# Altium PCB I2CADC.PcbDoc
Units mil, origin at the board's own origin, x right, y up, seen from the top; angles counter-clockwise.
Board outline 1475 x 800 mil, 2 copper layers (Top Layer, Bottom Layer), stack 61.855 mil thick; 14 components, 9 nets, 44 pads, 7 vias.
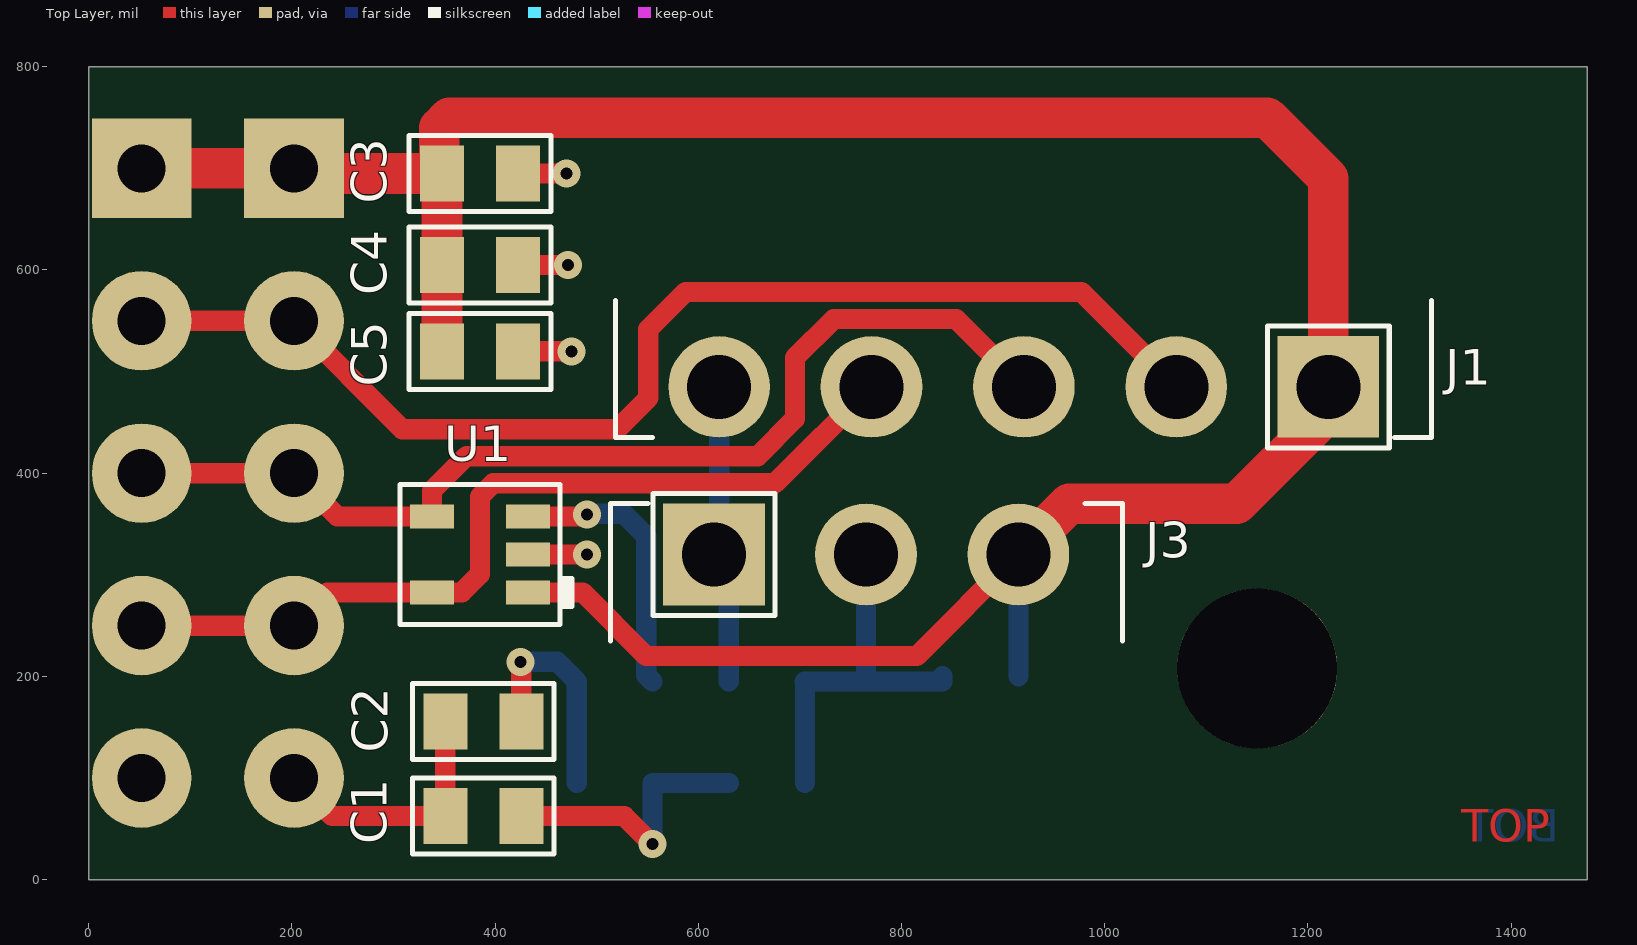
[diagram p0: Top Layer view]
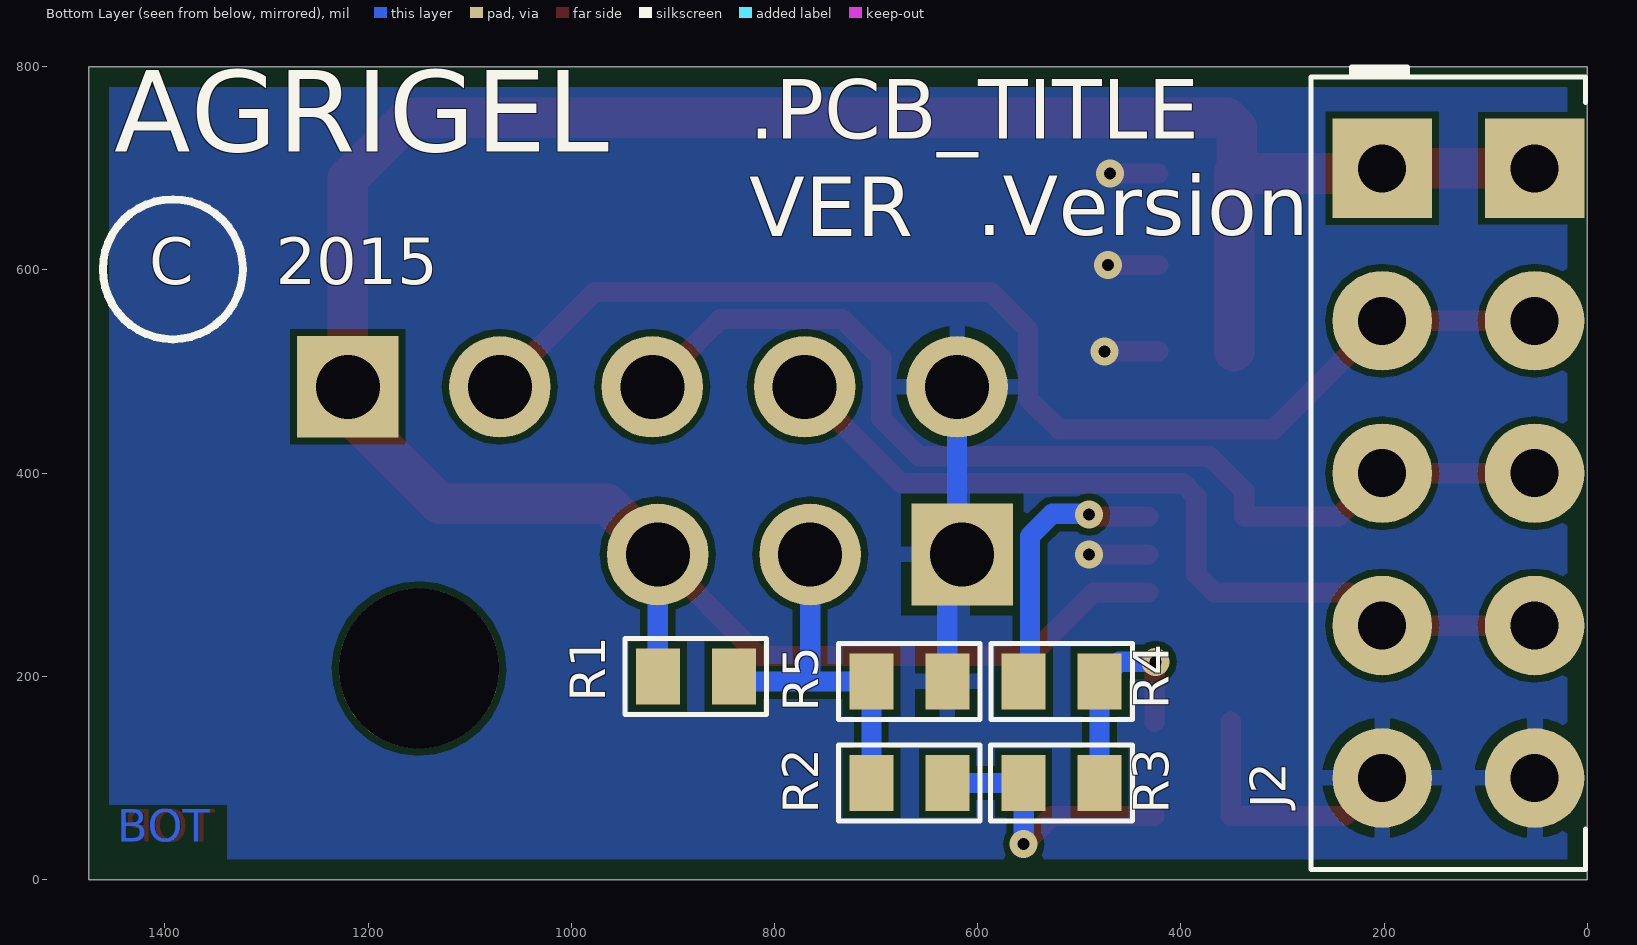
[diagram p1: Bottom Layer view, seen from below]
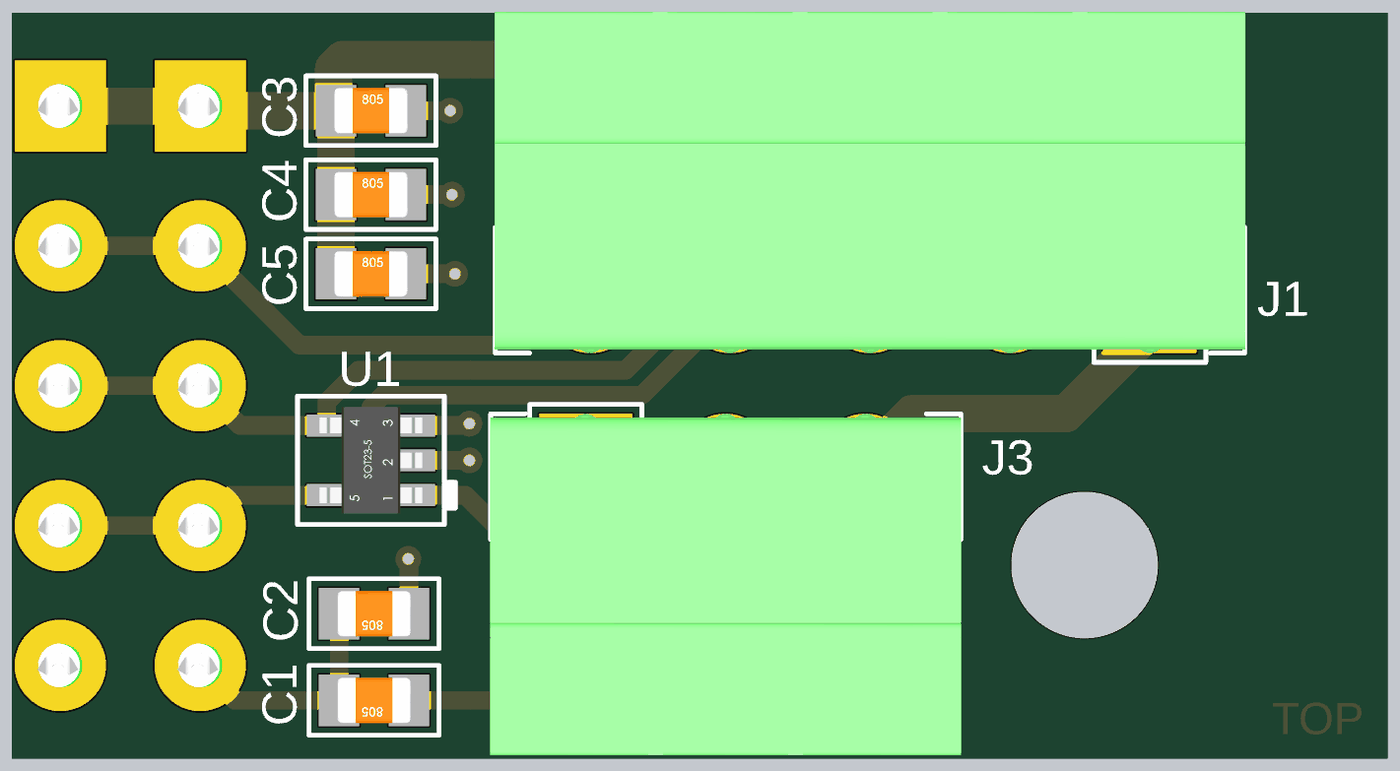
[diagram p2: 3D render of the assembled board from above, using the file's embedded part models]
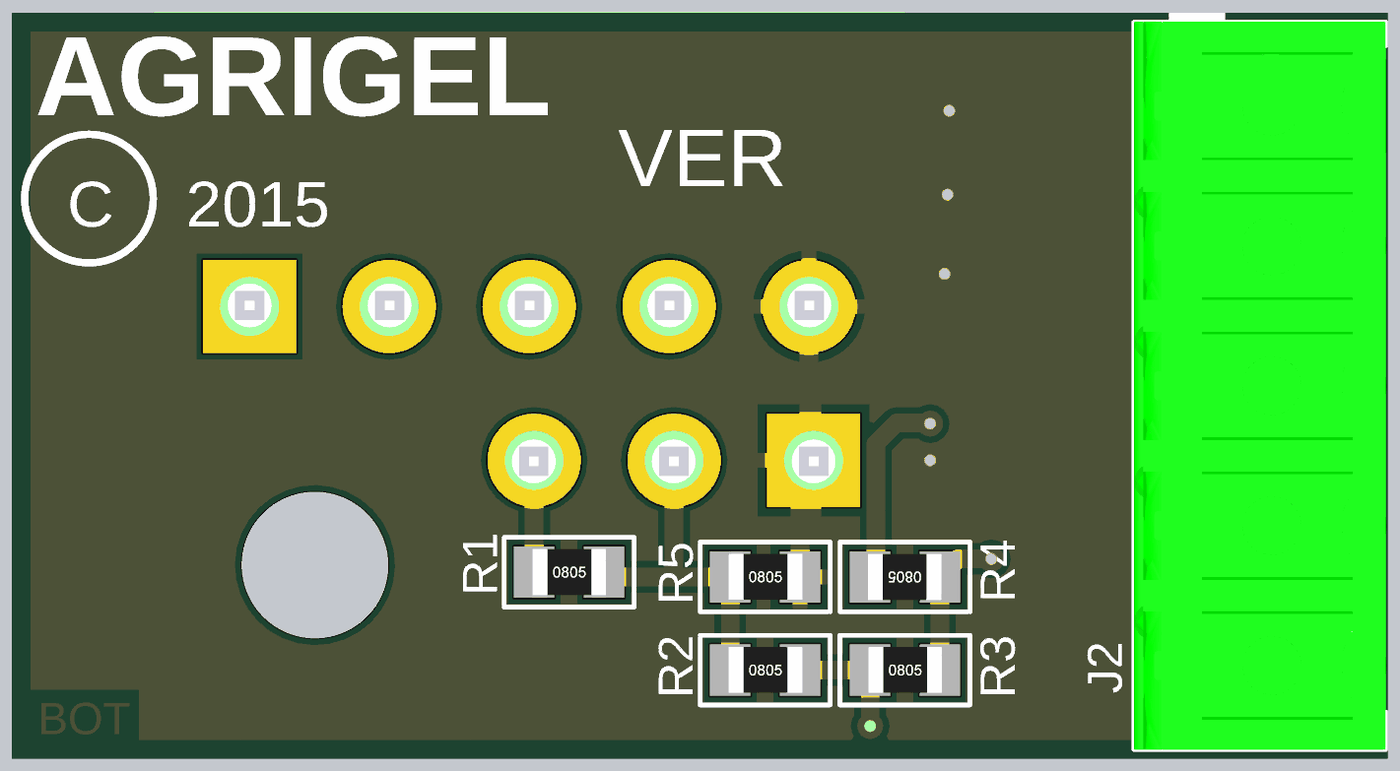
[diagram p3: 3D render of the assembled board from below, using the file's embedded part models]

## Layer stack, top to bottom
Top Layer: signal copper 1.4
Dielectric: prepreg 59.0551, FR-4, Dk 4.2
Bottom Layer: signal copper 1.4

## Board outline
0,0 0,800 1475,800 1475,0

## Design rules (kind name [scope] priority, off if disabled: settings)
Clearance [All] p1: gap=6.69
FabricationTestPointUsage TestPointUsage [All] p1: valid=0 allowmultiple=FALSE
FabricationTestpoint Testpoint [All] p1: side=3 testpointundercomponent=TRUE minsize=40 maxsize=100 preferedsize=60 minholesize=0 maxholesize=40 preferedholesize=32 testpointgrid=1 allowsidetop=TRUE allowsidebottom=TRUE usegrid=TRUE gridtolerance=0.01
HoleSize [All] p1: absolutevalues=TRUE maxlimit=196.85 minlimit=9.84 maxpercent=80.000 minpercent=20.000
PlaneClearance [All] p1: clearance=19.68
PolygonConnect PolygonConnectVia [All vs isvia] p1: connectstyle=Direct reliefconductorwidth=9.84 reliefentries=4 polygonreliefangle="90 Angle" airgapwidth=10
PolygonConnect [All] p2: connectstyle=Relief reliefconductorwidth=15.75 reliefentries=4 polygonreliefangle="90 Angle" airgapwidth=10
RoutingCorners [All] p1: cornerstyle=45-Degree minsetback=98.43 maxsetback=98.43
RoutingVias [All] p1: holewidth=11.81 width=27.56 viastyle="Through Hole" minholewidth=11.81 minwidth=27.56 maxholewidth=11.81 maxwidth=27.56
SilkToSolderMaskClearance SilkscreenOverComponentPads [IsPad] p1: minsilkscreentomaskgap=10 clearancetoexposedcopper=TRUE
SolderMaskExpansion [All] p1: expansion=1.97
Width "Width_High Power" [InNetClass('High Power')] p1: maxlimit=59.06 minlimit=19.68 preferedwidth=39.37
Width Width_Power [InNetClass('Power')] p2: maxlimit=39.37 minlimit=11.81 preferedwidth=19.68
Width [All] p3: maxlimit=78.74 minlimit=7.87 preferedwidth=7.87
22 further rules are at their usual default settings.

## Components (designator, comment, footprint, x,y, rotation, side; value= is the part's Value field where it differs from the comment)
C1 "100nF_C0805_50V_10%_X7R" CAPC0805X110N 388.33,62.55 r180 top
C2 "100nF_C0805_50V_10%_X7R" CAPC0805X110N 388.33,155.5 r180 top
C3 "100nF_C0805_50V_10%_X7R" CAPC0805X110N 385,695 r0 top
C4 "10nF_C0805_50V_10%_X7R" CAPC0805X110N 385,605 r0 top
C5 "1uF_C0805_50V_10%_X7R-DNF" CAPC0805X110N 385,520 r0 top
J1 "ECH381R-05P" ECH381R-05P 920,620 r0 top
J2 "IMCV 1,5/ 5-G-3,81" "IMCV 1,5/ 5-G-3,81" 127,400 r270 bottom
J3 "ECH381R-03P" ECH381R-03P 765.39,185 r180 top
R1 "10K_R0805_1%-DNF" RESC0805X65N 877.6,200 r180 bottom
R2 "1K_R0805_1%" RESC0805X65N 667.4,95 r180 bottom
R3 "1K_R0805_1%" RESC0805X65N 517.6,95 r180 bottom
R4 "1K_R0805_1%" RESC0805X65N 517.4,195 r0 bottom
R5 "10K_R0805_1%" RESC0805X65N 667.4,195 r180 bottom
U1 "MCP3021A0T-E/OT" SOT23-5 385,320 r180 top

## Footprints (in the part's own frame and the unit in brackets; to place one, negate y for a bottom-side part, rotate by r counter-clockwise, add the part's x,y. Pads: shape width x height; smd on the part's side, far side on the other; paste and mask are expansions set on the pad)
CAPC0805X110N [mm] "Chip Capacitor, 0805, 2-Leads, Body 2.0x1.3mm, IPC Medium Density"
  rect 1.1x1.4 smd paste+0 mask+0.05: 1(-0.95,0) 2(0.95,0)
  silkscreen extent -1.77,-0.95 1.77,0.95, body extent -1,-0.62 1,0.63, height 1.11
ECH381R-03P [mm] "ECH381R 12.22x9.2mm"
  rect 2.54x2.54 hole 1.6: 1(3.81,-3.429)
  round 2.54 hole 1.6: 2(0.01,-3.429) 3(-3.8,-3.429)
  silkscreen extent -6.4,-4.95 6.4,-1.27, body extent -6.41,-4.7 6.41,4.6, height 7.25
ECH381R-05P [mm] "ECH381R 19.84x9.2mm"
  rect 2.54x2.54 hole 1.6: 1(7.62,-3.429)
  round 2.54 hole 1.6: 2(3.82,-3.429) 3(0.01,-3.429) 4(-3.8,-3.429) 5(-7.61,-3.429)
  silkscreen extent -10.2,-4.95 10.2,-1.27, body extent -10.22,-4.7 10.22,4.6, height 7.25
"IMCV 1,5/ 5-G-3,81" [mil] "IMCV 1,5/ 5-G-3,81"
  rect 98x98 hole 47.24: 1(-300,-75) 1(-300,75)
  round 98 hole 47.24: 2(-150,-75) 2(-150,75) 3(0,-75) 3(0,75) 4(150,-75) 4(150,75) 5(300,-75) 5(300,75)
  silkscreen extent -400,-145 390,125, body extent -391,-145 391,125, height 571
RESC0805X65N [mm] "Chip Resistor, 0805, 2-Leads, Body 2.0x1.3mm, IPC Medium Density"
  rect 1.1x1.4 smd paste+0 mask+0.05: 1(-0.95,0) 2(0.95,0)
  silkscreen extent -1.77,-0.95 1.77,0.95, body extent -0.99,-0.62 1.01,0.63, height 0.6
SOT23-5 [mm] "SOT23, 5-Leads, Body 3.0x3.0mm (max), Pitch 0.95mm, IPC Medium Density"
  rect 1.1x0.6 smd paste+0 mask+0.05: 1(-1.2,0.95) 2(-1.2,0) 3(-1.2,-0.95) 4(1.2,-0.95) 5(1.2,0.95)
  silkscreen extent -2.3,-1.75 2,1.75, body extent -1.4,-1.45 1.4,1.45, height 1.14

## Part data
C1 C2 C3: library part 100nF_0805N_50V_10%_X7R_V, "Cap Ceramic X7R"
C4: library part 10nF_0805N_50V_10%_X7R_V, "Cap Ceramic X7R"
C5: library part 1uF_0805N_50V_10%_X7R_V-DNF, "Cap Ceramic X7R - Do not Fit"
J1 J3: "Header Pluggable 3.81mm Rt Angle"
J2: "Header Pluggable 3.81mm Vertical Female"
R1: library part 10K_0805_v-DNF, "Resistor Chip SMD - Do not Fit"
R2 R3 R4: library part 1K_0805_H, "Resistor Chip SMD"
R5: library part 10K_0805_V, "Resistor Chip SMD"
U1: library part MCP3021A0T-E/OT_SOT23, "IC 10-Bit A/D Converter with I2C"

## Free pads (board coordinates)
  round 157.48 hole 157.48 unplated mask+1: 0(1150,207.68)

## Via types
v1: diameter 27.56, hole 11.81, Top Layer to Bottom Layer, tented both sides, 7 vias

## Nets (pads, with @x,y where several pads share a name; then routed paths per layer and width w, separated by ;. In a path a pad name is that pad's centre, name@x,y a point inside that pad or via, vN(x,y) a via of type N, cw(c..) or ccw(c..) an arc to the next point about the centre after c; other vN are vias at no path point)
GND: C1.2 C2.2 C3.2 C4.2 C5.2 J1.5 J2.5 J3.1 R5.2 U1.2 | length 772.1
  Top Layer w20: J2.5@202,100 239.45,62.55 C1.2 C2.2 ; C5.2 v1(475.08,520) ; C4.2 v1(471.87,605) ; C3.2 v1(470,695) ; U1.2 v1(490.52,320)
  Bottom Layer w20: J1.5 620.39,325 J3.1 630,320 R5.2
NetC1_1: C1.1 R2.2 R3.1 | length 275.6
  Top Layer w20: C1.1 527.26,62.55 v1(554.8,35)
  Bottom Layer w19.68: R3.1 R2.2
  Bottom Layer w20: v1(554.8,35) 554.8,94.8 R3.1
NetC2_1: C2.1 R3.2 R4.1 | length 222.2
  Top Layer w20: v1(425,214.27) 425.73,213.54 C2.1
  Bottom Layer w20: v1(425,214.27) 460.93,214.27 480.2,195 R3.2
NetJ1_2: J1.2 J2.2 | length 1196.7
  Top Layer w20: J2.2@52,550 202,550 308.61,443.39 520,443.39 550.62,474.01 550.62,541.54 587.47,578.39 977.01,578.39 J1.2
NetJ1_3: J1.3 J2.3 U1.4 | length 1044.3
  Top Layer w20: J2.3@52,400 202,400 244.6,357.4 U1.4 337.76,382.76 371.69,416.69 658.33,416.69 695,453.36 695,513.62 733.07,551.69 853.7,551.69 J1.3
NetJ1_4: J1.4 J2.4 U1.5 | length 860.6
  Top Layer w20: J2.4@52,250 202,250 234.6,282.6 U1.5 367.28,282.6 385,300.31 385,376.99 398.01,390 675.39,390 J1.4
NetJ3_2: J3.2 R1.2 R2.1 R5.1 | length 365.4
  Bottom Layer w19.68: R2.1 R5.1
  Bottom Layer w20: R5.1 765,195 ; J3.2 765,195 ; R1.2 840.2,195 765,195
NetR4_2: R4.2 U1.3 | length 272.1
  Top Layer w20: U1.3 488.55,357.4 v1(490.52,359.37)
  Bottom Layer w20: v1(490.52,359.37) 491.15,360 526.61,360 548.7,337.91 548.7,201.1 R4.2
VCC: C3.1 C4.1 C5.1 J1.1 J2.1 J3.3 R1.1 U1.1 | length 2685.8
  Top Layer w20: J2.1@202,700 J2.1@207,695 ; U1.1 486.1,282.6 548.7,220 815,220 J3.3
  Top Layer w40: J2.1@52,700 J2.1@202,700 ; J2.1@207,695 C3.1 ; C5.1 C4.1 C3.1 ; J3.3 965,370 1130,370 1220,460 J1.1 1220,690 1160,750 355,750 345,740 345,697.6 C3.1
  Bottom Layer w20: R1.1 J3.3

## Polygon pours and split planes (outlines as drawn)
GND on Bottom Layer "GND_Bot" (solid, remove dead copper, pour order 2): 20,20 1455,20 1455,780 20,780

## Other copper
Top Layer:
  text "TOP" at 1350.68,26.38 h55
Bottom Layer:
  text "BOT" at 1447.18,26.38 h55

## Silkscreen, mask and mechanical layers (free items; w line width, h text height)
Bottom Overlay:
  circle w7.87: c1392.28,600.73 r68.9
  text ".PCB_TITLE" at 825,710 h100
  text "AGRIGEL" at 1450,690 h137.8
  text ".Version" at 601.27,614.95 h100
  text "VER" at 825.09,613.93 h100
  text "C    2015" at 1415.68,570.83 h78.74
Board:
  the board outline again, w2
